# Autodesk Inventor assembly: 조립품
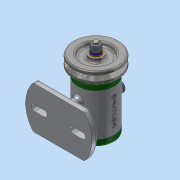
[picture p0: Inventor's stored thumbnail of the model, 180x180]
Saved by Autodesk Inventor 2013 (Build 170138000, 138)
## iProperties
Created: 2017-12
Part Number: 조립품
Document SubType Name: Assembly
Designer: dgall
Author: dgall
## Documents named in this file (14)
- C:\Users\dgall\Desktop\471207V1009\조립품.iam
- C:\Users\dgall\Desktop\471207V1009\본체.ipt
- C:\Users\dgall\Desktop\471207V1009\베어링 15 x 32 x 9.ipt
- C:\Users\dgall\Desktop\471207V1009\뒤커버.ipt
- C:\Users\dgall\Desktop\471207V1009\앞커버.ipt
- C:\Users\dgall\Desktop\471207V1009\축.ipt
- C:\Users\dgall\Desktop\471207V1009\오일 실 15 25 7.ipt
- C:\Users\dgall\Desktop\471207V1009\키 3 x 3 x 12.ipt
- C:\Users\dgall\Desktop\471207V1009\V벨트풀리.ipt
- C:\Users\dgall\Desktop\471207V1009\고무캡.ipt
- C:\Users\dgall\Desktop\471207V1009\스프링와셔 8.ipt
- C:\Users\dgall\Desktop\471207V1009\와셔 8x17.ipt
- C:\Users\dgall\Desktop\471207V1009\너트 M 8.ipt
- C:\Users\dgall\Desktop\471207V1009\볼트 M4 x 12.ipt
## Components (2 placed, 2 different names)
1. V벨트풀리:1
2. 고무캡:1
